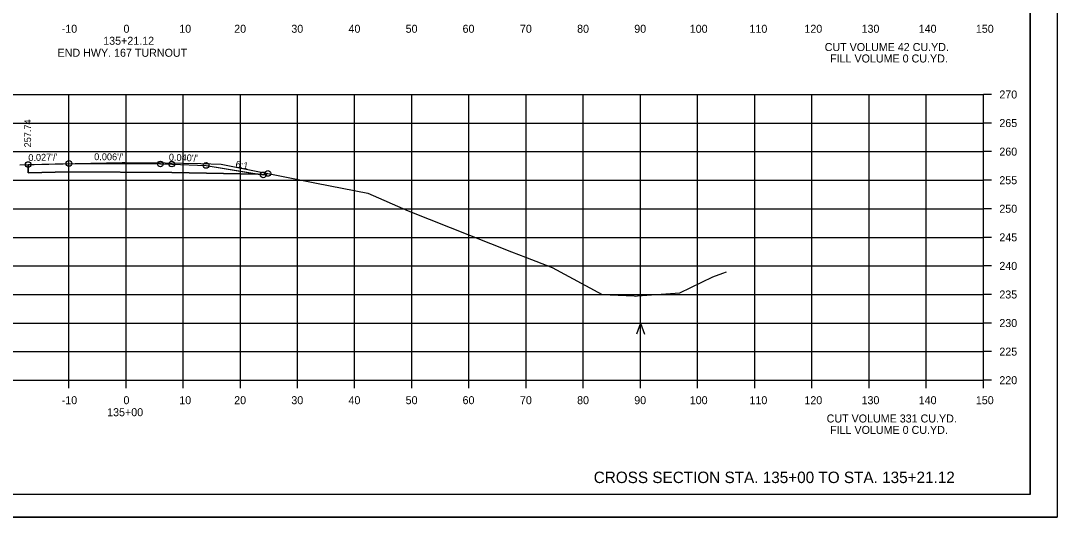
# Model space of a CAD drawing. Extents: x 1103485 to 1107180, y 2010593 to 2011873.
# Drawn here: x 1106998.8 to 1107180.1, y 2011659.5 to 2011746.4 of the extents above; entities that cross this region are included whole.
import ezdxf

# ---------------------------------------------------------------- set-up
doc = ezdxf.new("R2010")
doc.units = 0
for name, color, linetype in [('R_Alt Surface', 7, 'Continuous'), ('R_Axis', 7, 'Continuous'), ('R_Axis Annot', 7, 'Continuous'), ('R_Border', 7, 'Continuous'), ('R_Contours', 7, 'Continuous'), ('R_Draft', 7, 'Continuous'), ('R_Exist Surface', 7, 'Continuous'), ('R_Fin Surface', 7, 'Continuous'), ('R_Grid', 7, 'Continuous'), ('R_No Plot', 7, 'Continuous'), ('R_Proposed Const Limits', 7, 'Continuous'), ('R_Water Annot', 7, 'Continuous'), ('R_Xsect Elev', 7, 'Continuous'), ('R_Xsect Slope', 7, 'Continuous')]:
    doc.layers.add(name, color=color, linetype=linetype)

msp = doc.modelspace()

# ---------------------------------------------------------------- linework, layer by layer
at = {"layer": 'R_Alt Surface'}
msp.add_lwpolyline([(1107000.06, 2011721.25), (1107000.06, 2011719.79), (1107007.18, 2011719.98), (1107025.18, 2011719.88), (1107040.32, 2011719.58)], dxfattribs=at)
at = {"layer": 'R_Axis'}
for p, q in [((1107167.18, 2011683.51), (1107167.18, 2011733.51)), ((1107168.58, 2011733.51), (1107167.18, 2011733.51)), ((1107168.58, 2011728.51), (1107167.18, 2011728.51)), ((1107168.58, 2011723.51), (1107167.18, 2011723.51)), ((1107168.58, 2011718.51), (1107167.18, 2011718.51)), ((1107168.58, 2011713.51), (1107167.18, 2011713.51)), ((1107168.58, 2011708.51), (1107167.18, 2011708.51)), ((1107168.58, 2011703.51), (1107167.18, 2011703.51)), ((1107168.58, 2011698.51), (1107167.18, 2011698.51)), ((1107168.58, 2011693.51), (1107167.18, 2011693.51)), ((1107168.58, 2011688.51), (1107167.18, 2011688.51)), ((1106867.18, 2011683.51), (1107167.18, 2011683.51)), ((1107007.18, 2011682.11), (1107007.18, 2011683.51)), ((1107017.18, 2011682.11), (1107017.18, 2011683.51)), ((1107027.18, 2011682.11), (1107027.18, 2011683.51)), ((1107037.18, 2011682.11), (1107037.18, 2011683.51)), ((1107047.18, 2011682.11), (1107047.18, 2011683.51)), ((1107057.18, 2011682.11), (1107057.18, 2011683.51)), ((1107067.18, 2011682.11), (1107067.18, 2011683.51)), ((1107077.18, 2011682.11), (1107077.18, 2011683.51)), ((1107087.18, 2011682.11), (1107087.18, 2011683.51)), ((1107097.18, 2011682.11), (1107097.18, 2011683.51)), ((1107107.18, 2011682.11), (1107107.18, 2011683.51)), ((1107117.18, 2011682.11), (1107117.18, 2011683.51)), ((1107127.18, 2011682.11), (1107127.18, 2011683.51)), ((1107137.18, 2011682.11), (1107137.18, 2011683.51)), ((1107147.18, 2011682.11), (1107147.18, 2011683.51)), ((1107157.18, 2011682.11), (1107157.18, 2011683.51)), ((1107167.18, 2011682.11), (1107167.18, 2011683.51)), ((1107168.58, 2011683.51), (1107167.18, 2011683.51))]:
    msp.add_line(p, q, dxfattribs=at)
at = {"layer": 'R_Border'}
for q in [(1107175.36, 2011868.97), (1106859.18, 2011663.51)]:
    msp.add_line((1107175.36, 2011663.51), q, dxfattribs=at)
at = {"layer": 'R_Contours'}
msp.add_lwpolyline([(1107000.06, 2011721.25), (1107013.75, 2011721.54), (1107016.52, 2011721.6), (1107016.95, 2011721.6), (1107024.01, 2011721.54), (1107030.25, 2011721.43), (1107033.83, 2011721.32), (1107041.99, 2011719.7), (1107041.18, 2011719.43), (1107040.32, 2011719.58), (1107025.18, 2011719.88), (1107007.18, 2011719.98), (1107000.06, 2011719.79)], close=True, dxfattribs=at)
at = {"layer": 'R_Exist Surface'}
msp.add_lwpolyline([(1106998.58, 2011721.22), (1107013.75, 2011721.54), (1107016.52, 2011721.6), (1107016.95, 2011721.6), (1107024.01, 2011721.54), (1107030.25, 2011721.43), (1107033.83, 2011721.32), (1107050.49, 2011718.02), (1107059.49, 2011716.22), (1107066.53, 2011713.13), (1107084.62, 2011705.98), (1107087.06, 2011705.02), (1107091.75, 2011703.24), (1107100.46, 2011698.51), (1107106.09, 2011698.26), (1107106.29, 2011698.2), (1107106.65, 2011698.29), (1107114.05, 2011698.82), (1107119.86, 2011701.61), (1107121.59, 2011702.25), (1107122.24, 2011702.48)], dxfattribs=at)
at = {"layer": 'R_Fin Surface'}
for points in [[(1107000.06, 2011721.25), (1107007.18, 2011721.44), (1107023.18, 2011721.35), (1107025.18, 2011721.34), (1107031.18, 2011721.1), (1107040.32, 2011719.58), (1107041.18, 2011719.43), (1107041.99, 2011719.7)], [(1107000.06, 2011721.25), (1107007.18, 2011721.44), (1107023.18, 2011721.35), (1107025.18, 2011721.34), (1107031.18, 2011721.1)]]:
    msp.add_lwpolyline(points, dxfattribs=at)
at = {"layer": 'R_Grid'}
for p, q in [((1106867.18, 2011733.51), (1107167.18, 2011733.51)), ((1107007.18, 2011683.51), (1107007.18, 2011733.51)), ((1107017.18, 2011683.51), (1107017.18, 2011733.51)), ((1107027.18, 2011683.51), (1107027.18, 2011733.51)), ((1107037.18, 2011683.51), (1107037.18, 2011733.51)), ((1107047.18, 2011683.51), (1107047.18, 2011733.51)), ((1107057.18, 2011683.51), (1107057.18, 2011733.51)), ((1107067.18, 2011683.51), (1107067.18, 2011733.51)), ((1107077.18, 2011683.51), (1107077.18, 2011733.51)), ((1107087.18, 2011683.51), (1107087.18, 2011733.51)), ((1107097.18, 2011683.51), (1107097.18, 2011733.51)), ((1107107.18, 2011683.51), (1107107.18, 2011733.51)), ((1107117.18, 2011683.51), (1107117.18, 2011733.51)), ((1107127.18, 2011683.51), (1107127.18, 2011733.51)), ((1107137.18, 2011683.51), (1107137.18, 2011733.51)), ((1107147.18, 2011683.51), (1107147.18, 2011733.51)), ((1107157.18, 2011683.51), (1107157.18, 2011733.51)), ((1107167.18, 2011683.51), (1107167.18, 2011733.51)), ((1106867.18, 2011728.51), (1107167.18, 2011728.51)), ((1106867.18, 2011723.51), (1107167.18, 2011723.51)), ((1106867.18, 2011718.51), (1107167.18, 2011718.51)), ((1106867.18, 2011713.51), (1107167.18, 2011713.51)), ((1106867.18, 2011708.51), (1107167.18, 2011708.51)), ((1106867.18, 2011703.51), (1107167.18, 2011703.51)), ((1106867.18, 2011698.51), (1107167.18, 2011698.51)), ((1106867.18, 2011693.51), (1107167.18, 2011693.51)), ((1106867.18, 2011688.51), (1107167.18, 2011688.51)), ((1106867.18, 2011683.51), (1107167.18, 2011683.51))]:
    msp.add_line(p, q, dxfattribs=at)
at = {"layer": 'R_No Plot'}
msp.add_line((1106846.78, 2011659.53), (1107180.12, 2011659.53), dxfattribs=at)
for points in [[(1106846.78, 2011872.86), (1107180.12, 2011872.86), (1107180.12, 2011659.52), (1106846.78, 2011659.52)], [(1107093.1, 2011868.97), (1107093.1, 2011859.09), (1107128.84, 2011859.09), (1107128.84, 2011856.17), (1107152.04, 2011856.17), (1107152.04, 2011831.83), (1107175.36, 2011831.83), (1107175.36, 2011663.51), (1106859.18, 2011663.51), (1106859.18, 2011868.97)]]:
    msp.add_lwpolyline(points, close=True, dxfattribs=at)
for centre in [(1107000.06, 2011721.25), (1107007.18, 2011721.44), (1107023.18, 2011721.35), (1107025.18, 2011721.34), (1107031.18, 2011721.1), (1107041.18, 2011719.43), (1107041.99, 2011719.7)]:
    msp.add_circle(centre, 0.5, dxfattribs=at)
at = {"layer": 'R_Proposed Const Limits'}
msp.add_lwpolyline([(1107031.18, 2011721.1), (1107041.18, 2011719.43), (1107041.99, 2011719.7)], dxfattribs=at)
at = {"layer": 'R_Water Annot'}
for p, q in [((1107107.18, 2011693.51), (1107106.48, 2011691.58)), ((1107107.18, 2011687.22), (1107107.18, 2011693.51)), ((1107107.18, 2011693.51), (1107107.88, 2011691.58))]:
    msp.add_line(p, q, dxfattribs=at)

# ---------------------------------------------------------------- texts
at = {"layer": 'R_Axis Annot'}
for s, p in [('-10', (1107005.92, 2011744.31)), ('0', (1107016.73, 2011744.31)), ('10', (1107026.49, 2011744.31)), ('20', (1107036.1, 2011744.31)), ('30', (1107046.1, 2011744.31)), ('40', (1107056.1, 2011744.31)), ('50', (1107066.1, 2011744.31)), ('60', (1107076.06, 2011744.31)), ('70', (1107086.1, 2011744.31)), ('80', (1107096.1, 2011744.31)), ('90', (1107106.1, 2011744.31)), ('100', (1107115.81, 2011744.31)), ('110', (1107126.26, 2011744.31)), ('120', (1107135.87, 2011744.31)), ('130', (1107145.87, 2011744.31)), ('140', (1107155.87, 2011744.31)), ('150', (1107165.87, 2011744.31)), ('135+21.12', (1107013.18, 2011742.21)), ('END HWY. 167 TURNOUT', (1107005.2, 2011740.11)), ('CUT VOLUME 42 CU.YD.', (1107139.42, 2011741.11)), ('FILL VOLUME 0 CU.YD.', (1107140.37, 2011739.11)), ('270', (1107169.98, 2011732.81)), ('265', (1107169.98, 2011727.81)), ('260', (1107169.98, 2011722.81)), ('255', (1107169.98, 2011717.81)), ('250', (1107169.98, 2011712.81)), ('245', (1107169.98, 2011707.81)), ('240', (1107169.98, 2011702.81)), ('235', (1107169.98, 2011697.81)), ('230', (1107169.98, 2011692.81)), ('225', (1107169.98, 2011687.81)), ('220', (1107169.98, 2011682.81)), ('-10', (1107005.92, 2011679.31)), ('0', (1107016.73, 2011679.31)), ('10', (1107026.49, 2011679.31)), ('20', (1107036.1, 2011679.31)), ('30', (1107046.1, 2011679.31)), ('40', (1107056.1, 2011679.31)), ('50', (1107066.1, 2011679.31)), ('60', (1107076.06, 2011679.31)), ('70', (1107086.1, 2011679.31)), ('80', (1107096.1, 2011679.31)), ('90', (1107106.1, 2011679.31)), ('100', (1107115.81, 2011679.31)), ('110', (1107126.26, 2011679.31)), ('120', (1107135.87, 2011679.31)), ('130', (1107145.87, 2011679.31)), ('140', (1107155.87, 2011679.31)), ('150', (1107165.87, 2011679.31)), ('135+00', (1107013.87, 2011677.21)), ('CUT VOLUME 331 CU.YD.', (1107139.76, 2011676.11)), ('FILL VOLUME 0 CU.YD.', (1107140.37, 2011674.11))]:
    msp.add_text(s, height=1.4, dxfattribs=at).set_placement(p)
at = {"layer": 'R_Draft'}
msp.add_text('CROSS SECTION STA. 135+00 TO STA. 135+21.12', height=2, dxfattribs=at).set_placement((1107099.01, 2011665.51))
at = {"layer": 'R_Xsect Elev'}
msp.add_text('257.74', height=1.2, rotation=90, dxfattribs=at).set_placement((1107000.56, 2011724.25))
at = {"layer": 'R_Xsect Slope'}
for s, rotation, p in [("0.027'/'", 1.5466, (1107000.09, 2011721.85)), ("0.006'/'", 359.6769, (1107011.6, 2011722.02)), ("0.040'/'", 357.7094, (1107024.65, 2011721.96)), ('6:1', 350.5358, (1107036.27, 2011720.76))]:
    msp.add_text(s, height=1.2, rotation=rotation, dxfattribs=at).set_placement(p)

doc.saveas('drawing.dxf')
